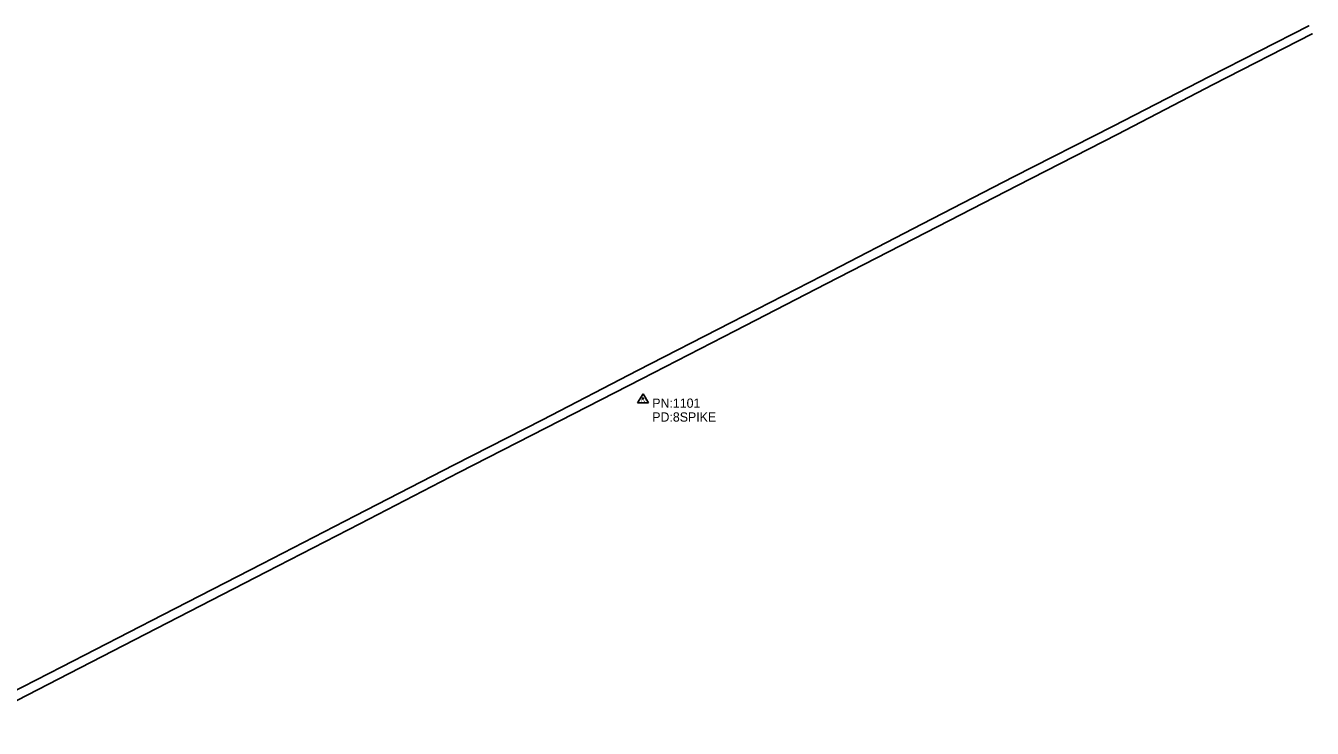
# Model space of a CAD drawing. Extents: x 1707085 to 1720058, y 548761 to 560063.
# Drawn here: x 1712754 to 1713450, y 550122 to 550502 of the extents above; entities that cross this region are included whole.
import ezdxf

# ---------------------------------------------------------------- set-up
doc = ezdxf.new("R2010")
doc.units = 0
for name, color, linetype in [('22', 7, 'Continuous'), ('R_Draft', 7, 'Continuous'), ('S_MSC_PT_SYM', 7, 'Continuous'), ('S_SECONDARY_CTL_ANNOT', 7, 'Continuous')]:
    doc.layers.add(name, color=color, linetype=linetype)

msp = doc.modelspace()

# ---------------------------------------------------------------- linework, layer by layer
at = {"layer": '22'}
for p, q in [((1713394.47, 550474.74), (1713448.13, 550502.15)), ((1713396.51, 550470.31), (1713450.03, 550497.74)), ((1713342.32, 550447.89), (1713394.47, 550474.74)), ((1713344.53, 550443.38), (1713396.51, 550470.31)), ((1713288.41, 550420.38), (1713342.32, 550447.89)), ((1713290.65, 550415.74), (1713344.53, 550443.38)), ((1713239.14, 550394.92), (1713288.41, 550420.38)), ((1713241.18, 550390.28), (1713290.65, 550415.74)), ((1713184.81, 550366.9), (1713239.14, 550394.92)), ((1713187.12, 550362.52), (1713241.18, 550390.28)), ((1713135.61, 550341.54), (1713184.81, 550366.9)), ((1713137.74, 550337.04), (1713187.12, 550362.52)), ((1713085.02, 550315.58), (1713135.61, 550341.54)), ((1713087.36, 550311.18), (1713137.74, 550337.04)), ((1713033.57, 550289.02), (1713085.02, 550315.58)), ((1713035.55, 550284.55), (1713087.36, 550311.18)), ((1712985.84, 550264.54), (1713033.57, 550289.02)), ((1712988.38, 550260.36), (1713035.55, 550284.55)), ((1712932.24, 550237.03), (1712985.84, 550264.54)), ((1712934.69, 550232.69), (1712988.38, 550260.36)), ((1712881.82, 550211.1), (1712932.24, 550237.03)), ((1712884.21, 550206.71), (1712934.69, 550232.69)), ((1712828.18, 550183.48), (1712881.82, 550211.1)), ((1712830.68, 550179.18), (1712884.21, 550206.71)), ((1712771.46, 550148.57), (1712830.68, 550179.18)), ((1712773.54, 550155.36), (1712828.18, 550183.48)), ((1712717.18, 550126.53), (1712773.54, 550155.36)), ((1712719.66, 550122.05), (1712771.46, 550148.57))]:
    msp.add_line(p, q, dxfattribs=at)
at = {"layer": 'R_Draft'}
for p, q in [((1713087.97, 550303.09), (1713084.96, 550298.14)), ((1713084.96, 550298.14), (1713090.92, 550298.14)), ((1713087.97, 550303.09), (1713090.92, 550298.14))]:
    msp.add_line(p, q, dxfattribs=at)
for radius in [0.311, 0.183, 0.103]:
    msp.add_circle((1713087.97, 550300.48), radius, dxfattribs=at)
at = {"layer": 'S_MSC_PT_SYM'}
for points in [[(1713448.13, 550502.15), (1713448.13, 550502.2), (1713448.13, 550502.15), (1713448.08, 550502.15), (1713448.13, 550502.15), (1713448.13, 550502.1), (1713448.13, 550502.15), (1713448.18, 550502.15)], [(1713450.03, 550497.74), (1713450.03, 550497.79), (1713450.03, 550497.74), (1713449.98, 550497.74), (1713450.03, 550497.74), (1713450.03, 550497.69), (1713450.03, 550497.74), (1713450.08, 550497.74)], [(1713394.47, 550474.74), (1713394.47, 550474.79), (1713394.47, 550474.74), (1713394.42, 550474.74), (1713394.47, 550474.74), (1713394.47, 550474.69), (1713394.47, 550474.74), (1713394.52, 550474.74)], [(1713396.51, 550470.31), (1713396.51, 550470.36), (1713396.51, 550470.31), (1713396.46, 550470.31), (1713396.51, 550470.31), (1713396.51, 550470.26), (1713396.51, 550470.31), (1713396.56, 550470.31)], [(1713342.32, 550447.89), (1713342.32, 550447.94), (1713342.32, 550447.89), (1713342.27, 550447.89), (1713342.32, 550447.89), (1713342.32, 550447.84), (1713342.32, 550447.89), (1713342.37, 550447.89)], [(1713344.53, 550443.38), (1713344.53, 550443.43), (1713344.53, 550443.38), (1713344.48, 550443.38), (1713344.53, 550443.38), (1713344.53, 550443.33), (1713344.53, 550443.38), (1713344.58, 550443.38)], [(1713288.41, 550420.38), (1713288.41, 550420.43), (1713288.41, 550420.38), (1713288.36, 550420.38), (1713288.41, 550420.38), (1713288.41, 550420.33), (1713288.41, 550420.38), (1713288.46, 550420.38)], [(1713290.65, 550415.74), (1713290.65, 550415.79), (1713290.65, 550415.74), (1713290.6, 550415.74), (1713290.65, 550415.74), (1713290.65, 550415.69), (1713290.65, 550415.74), (1713290.7, 550415.74)], [(1713239.14, 550394.92), (1713239.14, 550394.97), (1713239.14, 550394.92), (1713239.09, 550394.92), (1713239.14, 550394.92), (1713239.14, 550394.87), (1713239.14, 550394.92), (1713239.19, 550394.92)], [(1713241.18, 550390.28), (1713241.18, 550390.33), (1713241.18, 550390.28), (1713241.13, 550390.28), (1713241.18, 550390.28), (1713241.18, 550390.23), (1713241.18, 550390.28), (1713241.23, 550390.28)], [(1713184.81, 550366.9), (1713184.81, 550366.95), (1713184.81, 550366.9), (1713184.76, 550366.9), (1713184.81, 550366.9), (1713184.81, 550366.85), (1713184.81, 550366.9), (1713184.86, 550366.9)], [(1713187.12, 550362.52), (1713187.12, 550362.57), (1713187.12, 550362.52), (1713187.07, 550362.52), (1713187.12, 550362.52), (1713187.12, 550362.47), (1713187.12, 550362.52), (1713187.18, 550362.52)], [(1713135.61, 550341.54), (1713135.61, 550341.59), (1713135.61, 550341.54), (1713135.56, 550341.54), (1713135.61, 550341.54), (1713135.61, 550341.49), (1713135.61, 550341.54), (1713135.66, 550341.54)], [(1713137.74, 550337.04), (1713137.74, 550337.09), (1713137.74, 550337.04), (1713137.69, 550337.04), (1713137.74, 550337.04), (1713137.74, 550336.99), (1713137.74, 550337.04), (1713137.79, 550337.04)], [(1713085.02, 550315.58), (1713085.02, 550315.63), (1713085.02, 550315.58), (1713084.97, 550315.58), (1713085.02, 550315.58), (1713085.02, 550315.53), (1713085.02, 550315.58), (1713085.07, 550315.58)], [(1713087.36, 550311.18), (1713087.36, 550311.23), (1713087.36, 550311.18), (1713087.31, 550311.18), (1713087.36, 550311.18), (1713087.36, 550311.13), (1713087.36, 550311.18), (1713087.41, 550311.18)], [(1713033.57, 550289.02), (1713033.57, 550289.07), (1713033.57, 550289.02), (1713033.52, 550289.02), (1713033.57, 550289.02), (1713033.57, 550288.97), (1713033.57, 550289.02), (1713033.62, 550289.02)], [(1713035.55, 550284.55), (1713035.55, 550284.6), (1713035.55, 550284.55), (1713035.5, 550284.55), (1713035.55, 550284.55), (1713035.55, 550284.5), (1713035.55, 550284.55), (1713035.6, 550284.55)], [(1712985.84, 550264.54), (1712985.84, 550264.59), (1712985.84, 550264.54), (1712985.79, 550264.54), (1712985.84, 550264.54), (1712985.84, 550264.49), (1712985.84, 550264.54), (1712985.89, 550264.54)], [(1712988.38, 550260.36), (1712988.38, 550260.41), (1712988.38, 550260.36), (1712988.33, 550260.36), (1712988.38, 550260.36), (1712988.38, 550260.31), (1712988.38, 550260.36), (1712988.43, 550260.36)], [(1712932.24, 550237.03), (1712932.24, 550237.08), (1712932.24, 550237.03), (1712932.19, 550237.03), (1712932.24, 550237.03), (1712932.24, 550236.98), (1712932.24, 550237.03), (1712932.29, 550237.03)], [(1712934.69, 550232.69), (1712934.69, 550232.74), (1712934.69, 550232.69), (1712934.64, 550232.69), (1712934.69, 550232.69), (1712934.69, 550232.64), (1712934.69, 550232.69), (1712934.74, 550232.69)], [(1712881.82, 550211.1), (1712881.82, 550211.15), (1712881.82, 550211.1), (1712881.77, 550211.1), (1712881.82, 550211.1), (1712881.82, 550211.05), (1712881.82, 550211.1), (1712881.87, 550211.1)], [(1712884.21, 550206.71), (1712884.21, 550206.76), (1712884.21, 550206.71), (1712884.16, 550206.71), (1712884.21, 550206.71), (1712884.21, 550206.66), (1712884.21, 550206.71), (1712884.26, 550206.71)], [(1712828.18, 550183.48), (1712828.18, 550183.53), (1712828.18, 550183.48), (1712828.13, 550183.48), (1712828.18, 550183.48), (1712828.18, 550183.43), (1712828.18, 550183.48), (1712828.23, 550183.48)], [(1712830.68, 550179.18), (1712830.68, 550179.23), (1712830.68, 550179.18), (1712830.63, 550179.18), (1712830.68, 550179.18), (1712830.68, 550179.13), (1712830.68, 550179.18), (1712830.73, 550179.18)], [(1712773.54, 550155.36), (1712773.54, 550155.41), (1712773.54, 550155.36), (1712773.49, 550155.36), (1712773.54, 550155.36), (1712773.54, 550155.31), (1712773.54, 550155.36), (1712773.59, 550155.36)], [(1712771.46, 550148.57), (1712771.46, 550148.62), (1712771.46, 550148.57), (1712771.41, 550148.57), (1712771.46, 550148.57), (1712771.46, 550148.52), (1712771.46, 550148.57), (1712771.51, 550148.57)]]:
    msp.add_lwpolyline(points, dxfattribs=at)

# ---------------------------------------------------------------- texts
at = {"layer": 'R_Draft'}
msp.add_text('TV', height=1.5, rotation=360, dxfattribs=at).set_placement((1713086.77, 550298.47))
at = {"layer": 'S_SECONDARY_CTL_ANNOT'}
for s, p in [('PN:1101', (1713092.97, 550295.48)), ('PD:8SPIKE', (1713092.97, 550287.98))]:
    msp.add_text(s, height=5, dxfattribs=at).set_placement(p)

doc.saveas('drawing.dxf')
